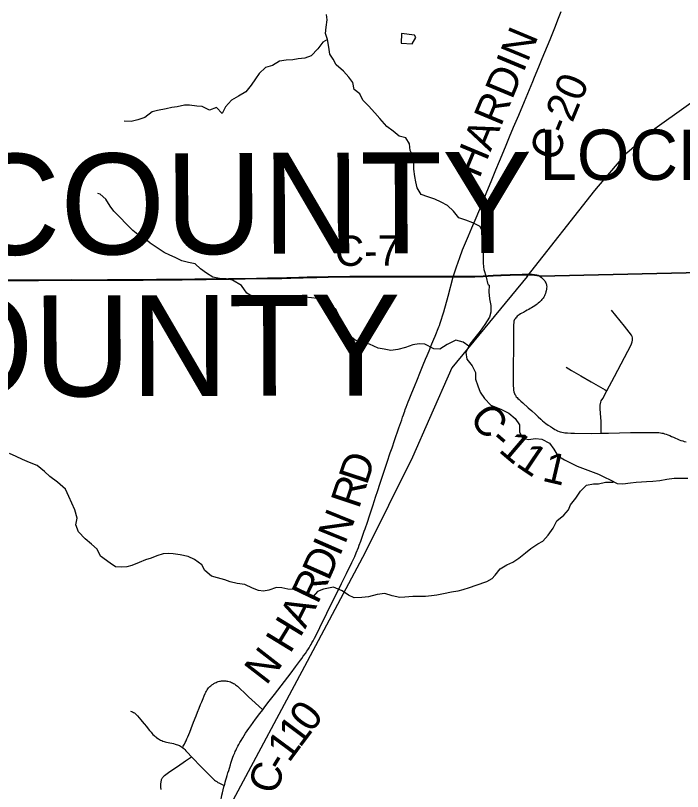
# Model space of a CAD drawing. Extents: x -87 to 2145, y -2128 to 440.
# Drawn here: x 154.23 to 187.3, y -1069.26 to -1030.81 of the extents above; entities that cross this region are included whole.
import ezdxf

# ---------------------------------------------------------------- set-up
doc = ezdxf.new("R2010")
doc.units = 0
for name, color, linetype in [('GM_X_Corporation_Text', 7, 'Continuous'), ('GM_X_County_Road', 7, 'Continuous'), ('GM_X_County_Road_Text', 7, 'Continuous'), ('GM_X_County_Text', 7, 'Continuous'), ('GM_X_Minor_Lake', 7, 'Continuous'), ('GM_X_Minor_River', 7, 'Continuous'), ('GM_X_Rail_Line', 7, 'Continuous'), ('GM_X_Township', 7, 'Continuous'), ('GM_X_Township_Road', 7, 'Continuous'), ('SH_Cut_Line', 7, 'Continuous')]:
    doc.layers.add(name, color=color, linetype=linetype)

msp = doc.modelspace()

# ---------------------------------------------------------------- linework, layer by layer
at = {"layer": 'GM_X_County_Road'}
for points in [[(175.933, -1043.758), (176.09, -1043.259), (176.255, -1042.796), (176.397, -1042.429), (176.685, -1041.733), (176.86, -1041.326), (177.067, -1040.843), (177.412, -1040.011), (177.598, -1039.555), (177.809, -1039.039), (178.049, -1038.464), (178.233, -1038.026), (178.527, -1037.313), (178.727, -1036.828), (178.929, -1036.344), (179.179, -1035.755), (179.46, -1035.072), (179.878, -1034.074), (179.967, -1033.862), (180.18, -1033.347), (180.348, -1032.938), (180.738, -1031.998), (180.974, -1031.421), (181.159, -1030.947), (181.281, -1030.606)], [(153.731, -1043.936), (155.371, -1043.936), (156.618, -1043.932), (157.028, -1043.93), (157.947, -1043.931), (158.799, -1043.926), (159.423, -1043.926), (159.997, -1043.926), (160.554, -1043.921), (161.227, -1043.912), (161.866, -1043.906), (162.489, -1043.905), (163.129, -1043.897), (163.686, -1043.89), (164.801, -1043.875), (165.622, -1043.866), (166.737, -1043.843), (167.179, -1043.839), (167.442, -1043.838), (167.688, -1043.831), (167.885, -1043.824), (168.278, -1043.809), (168.49, -1043.802), (168.703, -1043.796), (169.179, -1043.786), (169.736, -1043.775), (170.326, -1043.767), (170.522, -1043.766), (170.67, -1043.766), (170.817, -1043.765), (171.178, -1043.763), (171.735, -1043.763), (172.277, -1043.762), (172.654, -1043.76), (173.359, -1043.757), (173.835, -1043.759), (174.031, -1043.759), (174.523, -1043.755), (174.998, -1043.753), (175.933, -1043.758)], [(171.274, -1057.064), (171.352, -1056.86), (171.525, -1056.364), (171.568, -1056.24), (171.676, -1055.913), (171.779, -1055.601), (171.959, -1055.057), (172.01, -1054.901), (172.097, -1054.637), (172.172, -1054.403), (172.31, -1053.982), (172.356, -1053.842), (172.656, -1052.939), (172.805, -1052.488), (172.898, -1052.226), (173.024, -1051.87), (173.236, -1051.248), (173.377, -1050.845), (173.425, -1050.71), (173.461, -1050.602), (173.5, -1050.491), (173.529, -1050.411), (173.557, -1050.33), (173.603, -1050.211), (173.647, -1050.092), (173.698, -1049.962), (173.748, -1049.834), (173.815, -1049.671), (173.883, -1049.508), (174.013, -1049.187), (174.154, -1048.833), (174.28, -1048.527), (174.447, -1048.119), (174.56, -1047.841), (174.633, -1047.663), (174.735, -1047.42), (174.876, -1047.086), (174.926, -1046.967), (174.972, -1046.856), (175.037, -1046.695), (175.1, -1046.541), (175.154, -1046.405), (175.189, -1046.318), (175.217, -1046.242), (175.245, -1046.166), (175.284, -1046.058), (175.32, -1045.954), (175.354, -1045.853), (175.404, -1045.695), (175.467, -1045.491), (175.675, -1044.719), (175.933, -1043.758)], [(175.933, -1043.758), (176.997, -1043.753), (177.423, -1043.743), (177.914, -1043.716), (178.306, -1043.697), (178.764, -1043.677), (179.058, -1043.667), (179.352, -1043.658), (179.613, -1043.658), (179.678, -1043.659), (179.852, -1043.66), (179.969, -1043.669), (180.082, -1043.686), (180.169, -1043.712), (180.247, -1043.738)], [(180.247, -1043.738), (180.31, -1043.794), (180.352, -1043.837), (180.382, -1043.865), (180.41, -1043.893), (180.441, -1043.926), (180.471, -1043.965), (180.499, -1044.006), (180.521, -1044.05), (180.543, -1044.1), (180.558, -1044.147), (180.562, -1044.195), (180.567, -1044.251), (180.564, -1044.317), (180.556, -1044.375), (180.54, -1044.447), (180.525, -1044.51), (180.504, -1044.581), (180.477, -1044.651), (180.451, -1044.703), (180.419, -1044.764), (180.386, -1044.811), (180.358, -1044.85), (180.328, -1044.889), (180.289, -1044.935), (180.25, -1044.976), (180.208, -1045.017), (180.152, -1045.065), (180.1, -1045.106), (180.037, -1045.152), (179.974, -1045.193), (179.892, -1045.245), (179.816, -1045.291), (179.755, -1045.328), (179.677, -1045.373), (179.599, -1045.419), (179.512, -1045.469), (179.416, -1045.521), (179.338, -1045.564), (179.273, -1045.601), (179.199, -1045.647), (179.149, -1045.682), (179.106, -1045.714), (179.063, -1045.753), (179.03, -1045.79), (178.998, -1045.833), (178.974, -1045.872), (178.952, -1045.912), (178.939, -1045.962), (178.935, -1046.011), (178.926, -1046.148), (178.917, -1046.361), (178.919, -1046.584), (178.919, -1047.205), (178.902, -1048.264), (178.9, -1048.55), (178.9, -1048.759), (178.902, -1048.937), (178.902, -1049.043), (178.906, -1049.156), (178.915, -1049.275), (178.926, -1049.369), (178.941, -1049.455), (178.965, -1049.536), (178.987, -1049.586), (179.013, -1049.631), (179.037, -1049.668), (179.06, -1049.703), (179.095, -1049.74), (179.141, -1049.785), (179.197, -1049.837), (179.286, -1049.92), (179.386, -1050.011), (179.651, -1050.252), (179.822, -1050.406), (180.004, -1050.573), (180.141, -1050.697), (180.271, -1050.812), (180.362, -1050.89), (180.449, -1050.962), (180.532, -1051.024), (180.645, -1051.105), (180.749, -1051.174), (180.857, -1051.244), (180.977, -1051.317), (181.048, -1051.356), (181.105, -1051.385), (181.178, -1051.417), (181.24, -1051.438), (181.315, -1051.458), (181.393, -1051.476), (181.46, -1051.487), (181.532, -1051.493), (181.605, -1051.498), (181.762, -1051.504), (181.948, -1051.509), (182.795, -1051.519), (183.268, -1051.511)], [(183.268, -1051.511), (183.631, -1051.504), (184.714, -1051.472), (185.567, -1051.467), (185.78, -1051.467), (185.933, -1051.469), (186.05, -1051.474), (186.133, -1051.48), (186.209, -1051.489), (186.276, -1051.5), (186.346, -1051.515), (186.415, -1051.532), (186.493, -1051.556), (186.576, -1051.587), (186.671, -1051.628), (186.756, -1051.667), (186.847, -1051.708), (186.951, -1051.756), (187.04, -1051.795), (187.135, -1051.834), (187.225, -1051.866), (187.309, -1051.895), (187.389, -1051.914), (187.484, -1051.935)], [(166.486, -1065.212), (166.591, -1065.076), (166.812, -1064.79), (167.066, -1064.46), (167.898, -1063.382), (168.114, -1063.093), (168.365, -1062.749), (168.427, -1062.666), (168.5, -1062.566), (168.607, -1062.42), (168.676, -1062.318), (168.728, -1062.236), (168.787, -1062.14), (168.839, -1062.054), (168.885, -1061.975), (168.93, -1061.895), (168.982, -1061.8), (169.056, -1061.661), (169.218, -1061.347), (169.319, -1061.14), (169.664, -1060.433), (169.902, -1059.947), (170.107, -1059.536), (170.402, -1058.951), (170.647, -1058.468), (170.912, -1057.921), (171.05, -1057.624), (171.128, -1057.443), (171.235, -1057.167), (171.274, -1057.064)], [(164.592, -1068.954), (164.603, -1068.913), (164.633, -1068.805), (164.664, -1068.694), (164.694, -1068.581), (164.727, -1068.471), (164.764, -1068.347), (164.801, -1068.223), (164.837, -1068.104), (164.885, -1067.948), (164.913, -1067.861), (164.948, -1067.759), (164.976, -1067.668), (165.013, -1067.561), (165.041, -1067.485), (165.067, -1067.418), (165.098, -1067.347), (165.124, -1067.284), (165.152, -1067.225), (165.185, -1067.154), (165.217, -1067.086), (165.254, -1067.017), (165.298, -1066.937), (165.354, -1066.839), (165.412, -1066.741), (165.495, -1066.609), (165.575, -1066.483), (165.642, -1066.381), (165.721, -1066.264), (165.799, -1066.149), (165.892, -1066.018), (166.014, -1065.853), (166.137, -1065.684), (166.348, -1065.396), (166.486, -1065.212)], [(164.207, -1070.474), (164.271, -1070.233), (164.31, -1070.087), (164.34, -1069.964), (164.373, -1069.838), (164.41, -1069.69), (164.44, -1069.564), (164.468, -1069.451), (164.497, -1069.336), (164.533, -1069.182), (164.568, -1069.041), (164.592, -1068.954)]]:
    msp.add_lwpolyline(points, dxfattribs=at)
at = {"layer": 'GM_X_Minor_Lake'}
for points in [[(174.007, -1031.784), (173.366, -1031.7), (173.356, -1032.173)], [(173.356, -1032.173), (173.898, -1032.215), (174.075, -1031.906), (174.007, -1031.784)]]:
    msp.add_lwpolyline(points, dxfattribs=at)
at = {"layer": 'GM_X_Minor_River'}
for points in [[(177.664, -1044.133), (177.581, -1043.775), (177.468, -1043.411), (177.435, -1043.078), (177.432, -1042.736), (177.42, -1042.343), (177.409, -1041.94), (177.416, -1041.598), (177.262, -1041.263), (176.905, -1041.085), (176.556, -1040.947), (176.207, -1040.839), (175.943, -1040.511), (175.657, -1040.223), (175.33, -1040.055), (175.021, -1039.908), (174.682, -1039.8), (174.343, -1039.672), (174.139, -1039.356), (174.085, -1039.053), (174.031, -1038.79), (173.978, -1038.427), (173.975, -1038.085), (173.961, -1037.823), (173.797, -1037.497), (173.763, -1037.174), (173.579, -1036.879), (173.259, -1036.781), (172.963, -1036.534), (172.637, -1036.305), (172.294, -1035.906), (172.048, -1035.639), (171.734, -1035.28), (171.459, -1035.012), (171.295, -1034.687), (171.028, -1034.48), (170.955, -1034.126), (170.76, -1033.86), (170.485, -1033.573), (170.13, -1033.253), (169.975, -1032.978), (169.82, -1032.723), (169.767, -1032.37), (169.704, -1032.006), (169.6, -1031.702), (169.637, -1031.38), (169.675, -1031.029), (169.65, -1030.756)], [(169.704, -1032.006), (169.471, -1032.122), (169.213, -1032.459), (168.884, -1032.814), (168.57, -1032.928), (168.248, -1032.952), (167.986, -1033.007), (167.644, -1033.019), (167.312, -1033.073), (166.966, -1033.287), (166.632, -1033.381), (166.315, -1033.676), (166.138, -1033.944), (165.911, -1034.261), (165.643, -1034.588), (165.287, -1034.812), (164.941, -1035.006), (164.643, -1035.332), (164.485, -1035.661), (164.2, -1035.373), (163.846, -1035.496), (163.488, -1035.317), (163.228, -1035.302), (162.857, -1035.244), (162.606, -1035.259), (162.253, -1035.332), (161.981, -1035.376), (161.708, -1035.431), (161.275, -1035.512), (161.002, -1035.587), (160.645, -1035.861), (160.301, -1035.975), (159.958, -1036.068), (159.617, -1036.041)], [(165.432, -1044.186), (164.984, -1043.932), (164.684, -1043.866), (164.343, -1043.848), (164.023, -1043.781), (163.706, -1043.573), (163.41, -1043.356), (163.133, -1043.118), (162.804, -1043.041), (162.484, -1042.964), (162.146, -1042.796), (161.887, -1042.68), (161.609, -1042.553), (161.262, -1042.324), (160.916, -1042.086), (160.659, -1041.879), (160.381, -1041.732), (160.045, -1041.463), (159.73, -1041.145), (159.396, -1040.796), (159.101, -1040.508), (158.925, -1040.252), (158.712, -1039.906), (158.426, -1039.668), (158.316, -1039.626)], [(176.702, -1047.203), (176.422, -1047.005), (176.062, -1046.896), (175.635, -1047.118), (175.268, -1047.352), (174.967, -1047.325), (174.53, -1047.094), (174.238, -1047.078), (173.936, -1047.131), (173.571, -1047.254), (173.187, -1047.366), (172.844, -1047.409), (172.503, -1047.341), (172.213, -1047.295), (171.785, -1047.104), (171.434, -1047.026), (171.065, -1046.897), (170.719, -1046.618), (170.536, -1046.271), (170.441, -1046.018), (170.267, -1045.672), (170.133, -1045.397), (169.728, -1045.046), (169.459, -1044.919), (169.18, -1044.832), (168.899, -1044.796), (168.598, -1044.769), (168.246, -1044.762), (167.843, -1044.803), (167.561, -1044.827), (167.308, -1044.892), (167.045, -1044.956), (166.663, -1044.978), (166.402, -1044.942), (166.034, -1044.773), (165.696, -1044.564), (165.432, -1044.186)], [(177.664, -1044.133), (177.711, -1044.165), (177.693, -1044.507), (177.736, -1044.85), (177.799, -1045.173), (177.792, -1045.505), (177.726, -1045.765), (177.497, -1046.123), (177.269, -1046.45), (177.01, -1046.776), (176.752, -1047.093), (176.562, -1047.511), (176.605, -1047.844), (176.879, -1048.172), (177.033, -1048.508), (177.036, -1048.83), (177.159, -1049.154), (177.273, -1049.479), (177.477, -1049.795), (177.792, -1050.124)], [(177.792, -1050.124), (178.328, -1050.332), (178.688, -1050.517), (179.006, -1050.772), (179.213, -1051.096), (179.219, -1051.438), (179.366, -1051.751), (179.657, -1051.814), (180.018, -1051.778), (180.329, -1051.802), (180.698, -1051.997), (180.925, -1052.301), (181.123, -1052.625), (181.451, -1052.83), (181.711, -1052.953), (182.07, -1053.138), (182.35, -1053.242), (182.739, -1053.397), (183.139, -1053.542), (183.439, -1053.686), (183.708, -1053.82), (184.067, -1053.994), (184.338, -1054.018), (184.72, -1053.972), (185.001, -1053.935), (185.272, -1053.918), (185.523, -1053.901), (185.824, -1053.884), (186.176, -1053.858), (186.528, -1053.791), (186.879, -1053.745), (187.562, -1053.733)], [(177.852, -1058.721), (177.58, -1058.869), (177.053, -1059.059), (176.719, -1059.172), (176.415, -1059.266), (176.162, -1059.33), (175.849, -1059.394), (175.446, -1059.466), (175.112, -1059.529), (174.86, -1059.563), (174.558, -1059.597), (174.286, -1059.601), (173.924, -1059.603), (173.541, -1059.635), (173.29, -1059.649), (172.9, -1059.56), (172.54, -1059.452), (172.157, -1059.503), (171.732, -1059.615), (171.399, -1059.658), (171.017, -1059.669), (170.749, -1059.533), (170.422, -1059.314), (170.003, -1059.144), (169.508, -1059.244), (169.204, -1059.347), (168.997, -1059.604), (168.647, -1059.546), (168.34, -1059.318), (168.07, -1059.252), (167.738, -1059.244), (167.428, -1059.167), (167.167, -1059.161), (166.792, -1059.294), (166.53, -1059.338), (166.279, -1059.312), (165.98, -1059.195), (165.602, -1059.006), (165.221, -1058.957), (164.881, -1058.869), (164.611, -1058.783), (164.242, -1058.684), (163.952, -1058.587), (163.616, -1058.318), (163.472, -1058.033), (163.105, -1057.774), (162.797, -1057.626), (162.396, -1057.537), (162.056, -1057.489), (161.805, -1057.473), (161.553, -1057.488), (161.239, -1057.591), (160.955, -1057.695), (160.682, -1057.79), (160.357, -1057.923), (160.002, -1058.066), (159.749, -1058.131), (159.497, -1058.155), (159.196, -1058.138), (158.918, -1057.951), (158.453, -1057.599), (158.28, -1057.263), (157.994, -1057.015), (157.688, -1056.747), (157.354, -1056.398), (157.221, -1056.043), (157.288, -1055.723), (157.176, -1055.308), (157.023, -1054.983), (156.879, -1054.648), (156.716, -1054.282), (156.312, -1053.931), (155.935, -1053.661), (155.67, -1053.404), (155.314, -1053.104), (154.925, -1052.965), (154.586, -1052.817), (154.258, -1052.658), (153.94, -1052.51)], [(177.852, -1058.721), (178.017, -1058.544), (178.261, -1058.235), (178.584, -1058.028), (178.887, -1057.901), (179.19, -1057.704), (179.524, -1057.437), (179.777, -1057.219), (180.121, -1056.992), (180.383, -1056.854), (180.637, -1056.566), (180.882, -1056.207), (181.077, -1055.858), (181.411, -1055.571), (181.645, -1055.312), (181.748, -1055.063), (182.012, -1054.724), (182.237, -1054.375), (182.541, -1054.087), (182.883, -1054.021), (183.134, -1054.014), (183.476, -1053.937), (183.857, -1053.942)]]:
    msp.add_lwpolyline(points, dxfattribs=at)
at = {"layer": 'GM_X_Rail_Line'}
for points in [[(179.598, -1043.751), (182.951, -1039.48), (184.534, -1037.618), (185.922, -1036.403), (195.245, -1029.751), (195.82, -1028.984), (196.055, -1027.801), (196.228, -1024.239), (197.084, -1017.088), (197.758, -1010.567), (197.975, -1009.888)], [(179.598, -1043.751), (175.867, -1048.262), (174.749, -1050.788), (173.916, -1052.703), (172.722, -1055.089), (171.564, -1057.417), (168.566, -1063.07), (165.001, -1069.716)]]:
    msp.add_lwpolyline(points, dxfattribs=at)
at = {"layer": 'GM_X_Township'}
for points in [[(153.725, -1043.922), (155.365, -1043.922), (156.612, -1043.918), (157.022, -1043.916), (157.94, -1043.917), (158.793, -1043.912), (159.416, -1043.912), (159.991, -1043.912), (160.548, -1043.907), (161.221, -1043.898), (161.86, -1043.892), (162.483, -1043.89), (163.123, -1043.882), (163.68, -1043.876), (164.795, -1043.861), (165.615, -1043.852), (166.731, -1043.829), (167.173, -1043.825), (167.436, -1043.823), (167.682, -1043.817), (167.879, -1043.81), (168.272, -1043.795), (168.484, -1043.788), (168.697, -1043.782), (169.173, -1043.772), (169.73, -1043.761), (170.319, -1043.753), (170.516, -1043.752), (170.663, -1043.752), (170.811, -1043.751), (171.172, -1043.749), (171.729, -1043.748), (172.27, -1043.748), (172.648, -1043.746), (173.353, -1043.743), (173.828, -1043.745), (174.025, -1043.745), (174.516, -1043.741), (174.992, -1043.739), (175.927, -1043.744), (176.991, -1043.739), (177.417, -1043.729), (177.908, -1043.701), (178.3, -1043.683), (178.758, -1043.663), (179.052, -1043.653), (179.346, -1043.644), (179.607, -1043.644), (179.672, -1043.645), (179.846, -1043.646), (179.963, -1043.655), (180.076, -1043.672), (180.163, -1043.698), (180.241, -1043.724), (201.212, -1043.248)], [(201.212, -1043.248), (180.241, -1043.724), (180.163, -1043.698), (180.076, -1043.672), (179.963, -1043.655), (179.846, -1043.646), (179.672, -1043.645), (179.607, -1043.644), (179.346, -1043.644), (179.052, -1043.653), (178.758, -1043.663), (178.3, -1043.683), (177.908, -1043.701), (177.417, -1043.729), (176.991, -1043.739), (175.927, -1043.744), (174.992, -1043.739), (174.516, -1043.741), (174.025, -1043.745), (173.828, -1043.745), (173.353, -1043.743), (172.648, -1043.746), (172.27, -1043.748), (171.729, -1043.748), (171.172, -1043.749), (170.811, -1043.751), (170.663, -1043.752), (170.516, -1043.752), (170.319, -1043.753), (169.73, -1043.761), (169.173, -1043.772), (168.697, -1043.782), (168.484, -1043.788), (168.272, -1043.795), (167.879, -1043.81), (167.682, -1043.817), (167.436, -1043.823), (167.173, -1043.825), (166.731, -1043.829), (165.615, -1043.852), (164.795, -1043.861), (163.68, -1043.876), (163.123, -1043.882), (162.483, -1043.89), (161.86, -1043.892), (161.221, -1043.898), (160.548, -1043.907), (159.991, -1043.912), (159.416, -1043.912), (158.793, -1043.912), (157.94, -1043.917), (157.022, -1043.916), (156.612, -1043.918), (155.365, -1043.922), (153.725, -1043.922)]]:
    msp.add_lwpolyline(points, dxfattribs=at)
at = {"layer": 'GM_X_Township_Road'}
for points in [[(183.268, -1051.511), (183.267, -1051.459), (183.265, -1051.235), (183.27, -1051.106), (183.272, -1050.931), (183.239, -1050.516), (183.223, -1050.3), (183.221, -1050.122), (183.244, -1049.976), (183.275, -1049.906), (183.342, -1049.781), (183.544, -1049.402), (183.921, -1048.693), (184.753, -1047.131), (184.81, -1046.98), (184.825, -1046.9), (184.828, -1046.836), (184.82, -1046.785), (184.805, -1046.72), (184.774, -1046.654), (184.424, -1046.205), (183.779, -1045.418)], [(181.535, -1048.241), (181.791, -1048.404), (182.258, -1048.66), (182.77, -1048.96), (183.459, -1049.353), (183.544, -1049.402)], [(162.506, -1067.079), (162.547, -1067.014), (162.577, -1066.969), (162.603, -1066.925), (162.651, -1066.836), (162.694, -1066.749), (162.733, -1066.66), (162.774, -1066.561), (162.82, -1066.446), (162.868, -1066.324), (162.942, -1066.142), (163.063, -1065.831), (163.182, -1065.519), (163.256, -1065.33), (163.335, -1065.135), (163.406, -1064.955), (163.462, -1064.816), (163.531, -1064.65), (163.582, -1064.529), (163.634, -1064.409), (163.664, -1064.345), (163.693, -1064.29), (163.727, -1064.228), (163.764, -1064.176), (163.808, -1064.124), (163.864, -1064.063), (163.909, -1064.022), (163.959, -1063.983), (164.024, -1063.94), (164.072, -1063.911), (164.125, -1063.882), (164.178, -1063.857), (164.231, -1063.835), (164.285, -1063.815), (164.344, -1063.798), (164.387, -1063.789), (164.444, -1063.78), (164.495, -1063.776), (164.545, -1063.775), (164.597, -1063.776), (164.663, -1063.782), (164.706, -1063.789), (164.762, -1063.8), (164.827, -1063.815), (164.888, -1063.835), (164.938, -1063.855), (164.99, -1063.88), (165.043, -1063.908), (165.088, -1063.937), (165.141, -1063.972), (165.183, -1064.006), (165.231, -1064.046), (165.313, -1064.121), (165.407, -1064.206), (165.557, -1064.349), (165.789, -1064.566), (166.117, -1064.869), (166.486, -1065.212)], [(159.928, -1065.277), (159.984, -1065.297), (160.034, -1065.318), (160.082, -1065.342), (160.125, -1065.37), (160.18, -1065.414), (160.232, -1065.466), (160.277, -1065.516), (160.36, -1065.616), (160.438, -1065.709), (160.51, -1065.796), (160.609, -1065.913), (160.718, -1066.043), (160.811, -1066.158), (160.883, -1066.245), (160.957, -1066.33), (160.998, -1066.377), (161.047, -1066.432), (161.1, -1066.482), (161.139, -1066.521), (161.185, -1066.56), (161.23, -1066.597), (161.28, -1066.631), (161.328, -1066.659), (161.375, -1066.688), (161.427, -1066.716), (161.484, -1066.744), (161.542, -1066.77), (161.599, -1066.792), (161.658, -1066.809), (161.725, -1066.822), (161.794, -1066.835), (161.885, -1066.853), (161.985, -1066.872), (162.068, -1066.892), (162.146, -1066.913), (162.204, -1066.933), (162.257, -1066.95), (162.309, -1066.97), (162.361, -1066.992), (162.417, -1067.02), (162.458, -1067.046), (162.506, -1067.079)], [(162.506, -1067.079), (162.575, -1067.139), (162.628, -1067.191), (162.684, -1067.252), (162.764, -1067.334), (162.964, -1067.547)], [(161.455, -1069.17), (161.442, -1069.046), (161.436, -1068.95), (161.438, -1068.878), (161.446, -1068.803), (161.456, -1068.751), (161.466, -1068.712), (161.478, -1068.676), (161.492, -1068.64), (161.511, -1068.606), (161.533, -1068.571), (161.559, -1068.532), (161.611, -1068.473), (161.677, -1068.419), (161.876, -1068.278), (162.255, -1068.022), (162.655, -1067.753), (162.964, -1067.547)], [(162.964, -1067.547), (163.071, -1067.661), (163.35, -1067.955), (163.521, -1068.128), (163.76, -1068.375), (163.964, -1068.578), (164.042, -1068.649), (164.097, -1068.695), (164.149, -1068.736), (164.208, -1068.777), (164.264, -1068.812), (164.312, -1068.84), (164.372, -1068.873), (164.442, -1068.903), (164.518, -1068.929), (164.592, -1068.954)]]:
    msp.add_lwpolyline(points, dxfattribs=at)
at = {"layer": 'SH_Cut_Line'}
msp.add_lwpolyline([(201.212, -1043.248), (180.241, -1043.724), (180.163, -1043.698), (180.076, -1043.672), (179.963, -1043.655), (179.846, -1043.646), (179.672, -1043.645), (179.607, -1043.644), (179.346, -1043.644), (179.052, -1043.653), (178.758, -1043.663), (178.3, -1043.683), (177.908, -1043.701), (177.417, -1043.729), (176.991, -1043.739), (175.927, -1043.744), (174.992, -1043.739), (174.516, -1043.741), (174.025, -1043.745), (173.828, -1043.745), (173.353, -1043.743), (172.648, -1043.746), (172.27, -1043.748), (171.729, -1043.748), (171.172, -1043.749), (170.811, -1043.751), (170.663, -1043.752), (170.516, -1043.752), (170.319, -1043.753), (169.73, -1043.761), (169.173, -1043.772), (168.697, -1043.782), (168.484, -1043.788), (168.272, -1043.795), (167.879, -1043.81), (167.682, -1043.817), (167.436, -1043.823), (167.173, -1043.825), (166.731, -1043.829), (165.615, -1043.852), (164.795, -1043.861), (163.68, -1043.876), (163.123, -1043.882), (162.483, -1043.89), (161.86, -1043.892), (161.221, -1043.898), (160.548, -1043.907), (159.991, -1043.912), (159.416, -1043.912), (158.793, -1043.912), (157.94, -1043.917), (157.022, -1043.916), (156.612, -1043.918), (155.365, -1043.922), (153.725, -1043.922)], dxfattribs=at)

# ---------------------------------------------------------------- texts
at = {"layer": 'GM_X_Corporation_Text'}
msp.add_text('LOCKINGTON', height=2.5, rotation=0, dxfattribs=at).set_placement((180.206, -1038.96))
at = {"layer": 'GM_X_County_Road_Text'}
for s, rotation, p in [('HARDIN', 67.4199, (177.224, -1038.926)), ('C-20', 67.5712, (181.033, -1038.116)), ('C-7', 0.2701, (170.071, -1043.221)), ('C', 307.5888, (176.684, -1050.764)), ('-', 318.9664, (177.658, -1051.976)), ('1', 319.4634, (178.133, -1052.39)), ('D', 71.6709, (171.645, -1054.127)), ('1', 326.0445, (178.985, -1053.105)), ('1', 346.8588, (180.294, -1053.857)), ('R', 71.4422, (171.251, -1055.301)), ('N', 67.9407, (170.564, -1057.053)), ('I', 66.3023, (170.298, -1057.66)), ('D', 66.0622, (169.76, -1058.873)), ('R', 64.3409, (169.206, -1060.028)), ('A', 63.1617, (168.595, -1061.236)), ('H', 58.5996, (167.843, -1062.476)), ('N', 52.1509, (166.657, -1064.044)), ('0', 52.9927, (168.891, -1066.399)), ('1', 53.0635, (168.336, -1067.137)), ('1', 53.5319, (167.789, -1067.878)), ('C', 73.2574, (167.176, -1069.463)), ('-', 58.8502, (167.491, -1068.374))]:
    msp.add_text(s, height=1.5, rotation=rotation, dxfattribs=at).set_placement(p)
at = {"layer": 'GM_X_County_Text'}
for s, rotation, p in [('SHELBY COUNTY', 0.2267, (123.392, -1042.787)), ('MIAMI COUNTY', 0.1487, (123.931, -1049.767))]:
    msp.add_text(s, height=5, rotation=rotation, dxfattribs=at).set_placement(p)

doc.saveas('drawing.dxf')
